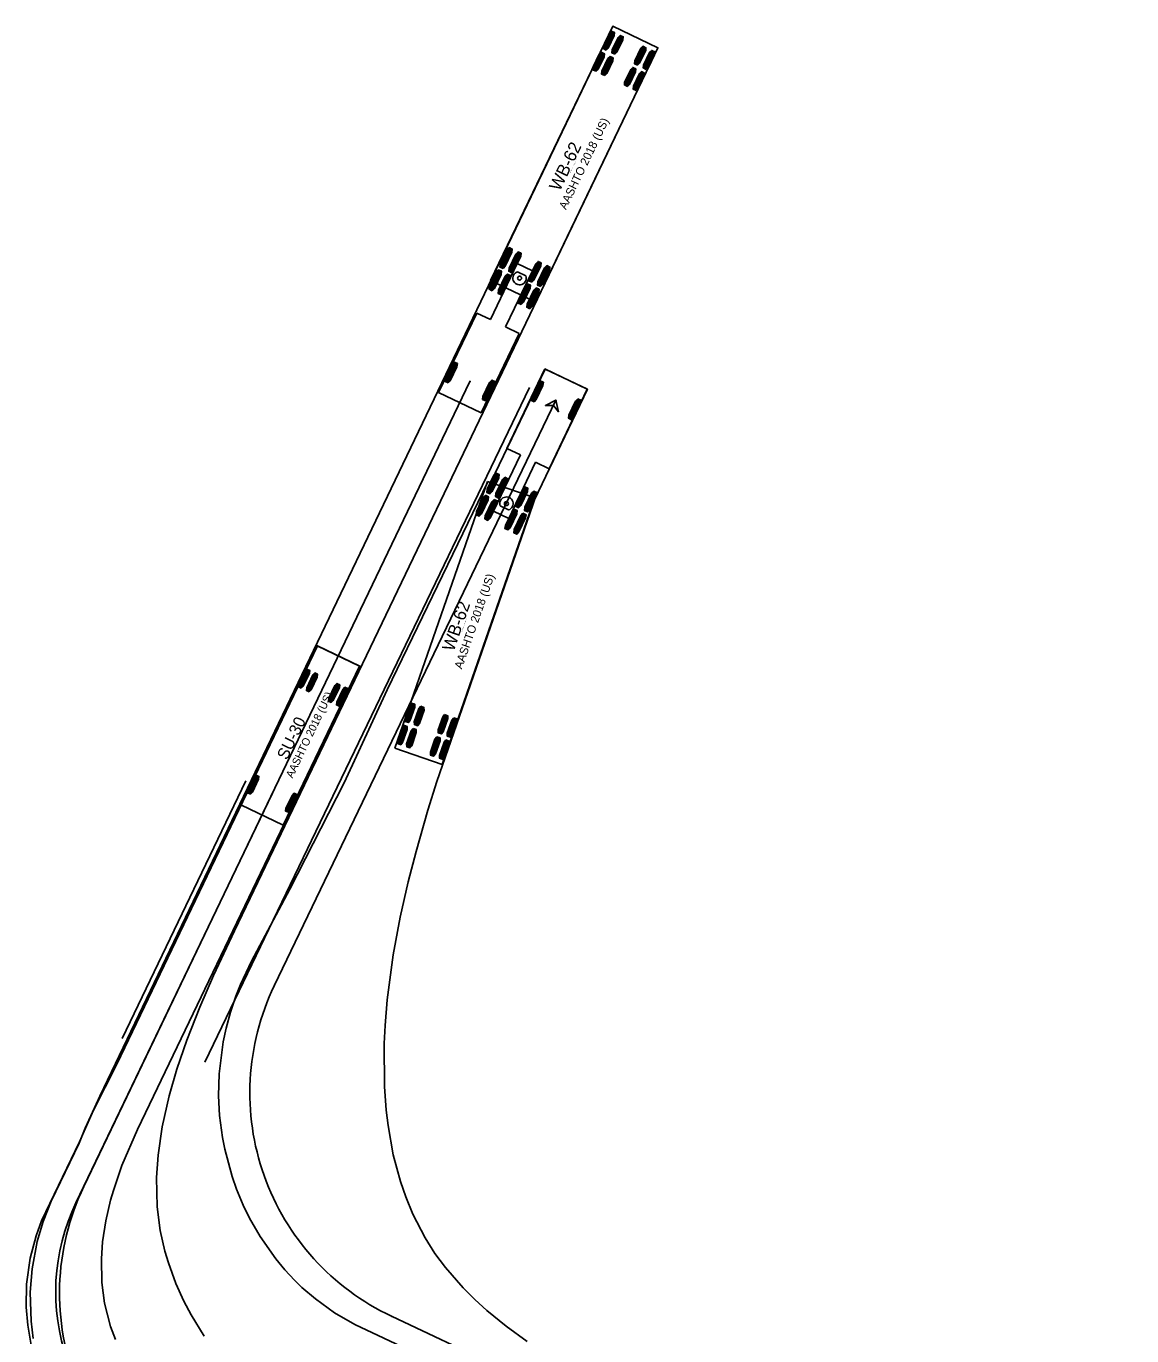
# Model space of a CAD drawing. Extents: x 186128 to 186702, y 352195 to 353183.
# Drawn here: x 186453 to 186641.2, y 352960 to 353182.7 of the extents above; entities that cross this region are included whole.
import ezdxf

# ---------------------------------------------------------------- set-up
doc = ezdxf.new("R2010")
doc.units = 0
doc.layers.add('SV_X_Control_Cells_Found', color=7, linetype='Continuous')
doc.layers.add('SV_X_Shot_Marker', color=7, linetype='Continuous')

msp = doc.modelspace()

# ---------------------------------------------------------------- linework, layer by layer
at = {"layer": 'SV_X_Control_Cells_Found'}
for p, q in [((186502.56, 353077.37), (186489.58, 353050.32)), ((186509.78, 353073.9), (186502.56, 353077.37)), ((186496.79, 353046.86), (186509.78, 353073.9)), ((186499.43, 353070.36), (186500.88, 353073.37)), ((186499.62, 353070.27), (186501.06, 353073.28)), ((186499.81, 353070.18), (186501.25, 353073.19)), ((186500.79, 353069.72), (186502.23, 353072.72)), ((186500.97, 353069.63), (186502.42, 353072.63)), ((186501.16, 353069.53), (186502.6, 353072.54)), ((186504.54, 353067.91), (186505.98, 353070.92)), ((186504.73, 353067.82), (186506.17, 353070.83)), ((186504.92, 353067.73), (186506.36, 353070.74)), ((186505.89, 353067.26), (186507.34, 353070.27)), ((186506.08, 353067.17), (186507.52, 353070.18)), ((186506.27, 353067.08), (186507.71, 353070.09)), ((186490.78, 353052.33), (186492.22, 353055.34)), ((186490.97, 353052.24), (186492.41, 353055.25)), ((186491.15, 353052.15), (186492.6, 353055.16)), ((186490.41, 353054.36), (186469.4, 353010.58)), ((186494.92, 353052.2), (186461.52, 352982.61)), ((186489.58, 353050.32), (186496.79, 353046.86)), ((186497.24, 353049.23), (186498.68, 353052.24)), ((186497.43, 353049.14), (186498.87, 353052.15)), ((186497.62, 353049.05), (186499.06, 353052.06)), ((186496.79, 353046.86), (186496.79, 353046.86))]:
    msp.add_line(p, q, dxfattribs=at)
for points in [[(186453.93, 352958.07), (186453.31, 352961.78), (186453.05, 352964.83), (186453.11, 352968.77), (186453.74, 352973.2), (186454.72, 352976.97), (186455.67, 352979.53), (186462.13, 352992.95), (186462.89, 352994.82), (186464.53, 352998.36), (186468.47, 353006.17), (186502.62, 353077.36), (186509.84, 353073.89), (186471.98, 352995.05), (186469.35, 352988.94), (186467.88, 352984.71), (186467.42, 352983.07), (186466.6, 352979.56), (186466.04, 352975.99), (186465.84, 352973.1), (186465.94, 352969.03), (186466.4, 352965.55), (186467.42, 352961.58), (186468.24, 352959.38)], [(186499.86, 353070.16), (186499.39, 353070.39), (186499.45, 353070.88), (186500.49, 353073.04), (186500.83, 353073.39), (186501.3, 353073.17), (186501.24, 353072.68), (186500.2, 353070.51), (186499.86, 353070.16)], [(186501.21, 353069.51), (186500.74, 353069.74), (186500.8, 353070.23), (186501.84, 353072.39), (186502.18, 353072.74), (186502.65, 353072.52), (186502.59, 353072.03), (186501.55, 353069.87), (186501.21, 353069.51)], [(186504.96, 353067.71), (186504.5, 353067.93), (186504.56, 353068.42), (186505.59, 353070.59), (186505.94, 353070.94), (186506.41, 353070.71), (186506.35, 353070.23), (186505.31, 353068.06), (186504.96, 353067.71)], [(186506.32, 353067.06), (186505.85, 353067.29), (186505.91, 353067.77), (186506.95, 353069.94), (186507.29, 353070.29), (186507.76, 353070.07), (186507.7, 353069.58), (186506.66, 353067.41), (186506.32, 353067.06)], [(186491.2, 353052.13), (186490.73, 353052.36), (186490.79, 353052.84), (186491.83, 353055.01), (186492.17, 353055.36), (186492.64, 353055.14), (186492.58, 353054.65), (186491.54, 353052.48), (186491.2, 353052.13)], [(186497.66, 353049.03), (186497.19, 353049.25), (186497.25, 353049.74), (186498.29, 353051.91), (186498.64, 353052.26), (186499.1, 353052.04), (186499.04, 353051.55), (186498.01, 353049.38), (186497.66, 353049.03)]]:
    msp.add_lwpolyline(points, dxfattribs=at)
for centre in [(186494.92, 353052.2), (186461.52, 352982.61), (186461.52, 352982.61)]:
    msp.add_circle(centre, 0.0417, dxfattribs=at)
msp.add_arc((186493.07, 352967.47), 35, 154.3603, 244.5505, dxfattribs=at)
at = {"layer": 'SV_X_Shot_Marker'}
for p, q in [((186552.86, 353182.75), (186532.09, 353139.47)), ((186551.28, 353178.91), (186552.7, 353181.88)), ((186551.48, 353178.81), (186552.91, 353181.78)), ((186551.69, 353178.71), (186553.12, 353181.68)), ((186560.53, 353179.07), (186552.86, 353182.75)), ((186552.76, 353178.19), (186554.19, 353181.17)), ((186552.97, 353178.09), (186554.4, 353181.07)), ((186553.18, 353177.99), (186554.6, 353180.97)), ((186556.62, 353176.34), (186558.05, 353179.31)), ((186539.76, 353135.79), (186560.53, 353179.07)), ((186549.54, 353175.3), (186550.97, 353178.27)), ((186549.75, 353175.2), (186551.18, 353178.18)), ((186549.96, 353175.1), (186551.39, 353178.08)), ((186551.03, 353174.59), (186552.46, 353177.56)), ((186551.24, 353174.49), (186552.67, 353177.46)), ((186551.45, 353174.39), (186552.87, 353177.36)), ((186556.83, 353176.24), (186558.26, 353179.21)), ((186557.04, 353176.14), (186558.47, 353179.11)), ((186558.11, 353175.62), (186559.54, 353178.6)), ((186558.32, 353175.52), (186559.75, 353178.5)), ((186558.53, 353175.43), (186559.95, 353178.4)), ((186554.89, 353172.73), (186556.32, 353175.71)), ((186555.1, 353172.63), (186556.53, 353175.61)), ((186555.31, 353172.53), (186556.74, 353175.51)), ((186556.38, 353172.02), (186557.81, 353174.99)), ((186556.59, 353171.92), (186558.02, 353174.89)), ((186556.79, 353171.82), (186558.22, 353174.79)), ((186533.72, 353141.76), (186535.31, 353145.06)), ((186533.93, 353141.66), (186535.52, 353144.97)), ((186534.14, 353141.56), (186535.72, 353144.87)), ((186535.21, 353141.05), (186536.8, 353144.35)), ((186535.42, 353140.95), (186537, 353144.25)), ((186535.62, 353140.85), (186537.21, 353144.15)), ((186536.62, 353142.4), (186532.04, 353132.84)), ((186539.21, 353141.16), (186536.62, 353142.4)), ((186538.62, 353139.41), (186540.21, 353142.71)), ((186538.83, 353139.31), (186540.42, 353142.61)), ((186539.04, 353139.21), (186540.62, 353142.52)), ((186540.11, 353138.69), (186541.7, 353142)), ((186540.32, 353138.6), (186541.9, 353141.9)), ((186540.52, 353138.5), (186542.11, 353141.8)), ((186531.91, 353137.97), (186533.49, 353141.28)), ((186532.09, 353139.47), (186539.76, 353135.79)), ((186532.11, 353137.87), (186533.7, 353141.18)), ((186532.32, 353137.77), (186533.91, 353141.08)), ((186533.39, 353137.26), (186534.98, 353140.56)), ((186533.6, 353137.16), (186535.19, 353140.47)), ((186533.81, 353137.06), (186535.39, 353140.37)), ((186534.62, 353131.6), (186539.21, 353141.16)), ((186538.09, 353140.27), (186536.63, 353140.97)), ((186536.8, 353135.62), (186538.39, 353138.93)), ((186537.01, 353135.52), (186538.6, 353138.83)), ((186537.22, 353135.42), (186538.8, 353138.73)), ((186538.29, 353134.91), (186539.88, 353138.21)), ((186538.5, 353134.81), (186540.09, 353138.11)), ((186538.71, 353134.71), (186540.29, 353138.02)), ((186539.76, 353135.79), (186539.76, 353135.79)), ((186529.72, 353133.96), (186523.23, 353120.43)), ((186532.04, 353132.84), (186529.72, 353133.96)), ((186530.45, 353116.97), (186536.94, 353130.49)), ((186536.94, 353130.49), (186534.62, 353131.6)), ((186524.38, 353122.29), (186525.96, 353125.59)), ((186524.58, 353122.19), (186526.17, 353125.49)), ((186524.79, 353122.09), (186526.38, 353125.39)), ((186541.32, 353124.46), (186534.84, 353110.93)), ((186548.53, 353121), (186541.32, 353124.46)), ((186541.32, 353124.46), (186541.32, 353124.46)), ((186462.85, 352985.38), (186528.57, 353122.31)), ((186530.76, 353119.22), (186532.35, 353122.53)), ((186530.97, 353119.12), (186532.56, 353122.43)), ((186531.18, 353119.02), (186532.76, 353122.33)), ((186540.59, 353122.4), (186539, 353119.1)), ((186540.8, 353122.3), (186539.21, 353119)), ((186541.01, 353122.2), (186539.42, 353118.9)), ((186483.46, 353006.54), (186538.69, 353121.29)), ((186495.26, 353019.53), (186543.2, 353119.12)), ((186523.23, 353120.43), (186530.45, 353116.97)), ((186542.05, 353107.47), (186548.53, 353121)), ((186546.98, 353119.34), (186545.39, 353116.04)), ((186547.19, 353119.24), (186545.6, 353115.94)), ((186547.39, 353119.14), (186545.8, 353115.84)), ((186530.45, 353116.97), (186530.45, 353116.97)), ((186534.84, 353110.93), (186537.15, 353109.82)), ((186537.15, 353109.82), (186532.57, 353100.26)), ((186535.16, 353099.02), (186539.74, 353108.58)), ((186539.74, 353108.58), (186542.05, 353107.47)), ((186533.07, 353106.71), (186531.49, 353103.4)), ((186533.28, 353106.61), (186531.69, 353103.31)), ((186533.48, 353106.51), (186531.9, 353103.21)), ((186534.56, 353106), (186532.97, 353102.69)), ((186534.76, 353105.9), (186533.18, 353102.59)), ((186534.97, 353105.8), (186533.39, 353102.49)), ((186531.58, 353105.29), (186515.79, 353059.96)), ((186539.61, 353102.5), (186531.58, 353105.29)), ((186531.58, 353105.29), (186531.58, 353105.29)), ((186537.97, 353104.36), (186536.39, 353101.06)), ((186538.18, 353104.26), (186536.59, 353100.96)), ((186538.38, 353104.17), (186536.8, 353100.86)), ((186539.46, 353103.65), (186537.87, 353100.34)), ((186539.66, 353103.55), (186538.08, 353100.24)), ((186523.82, 353057.17), (186539.61, 353102.5)), ((186531.25, 353102.92), (186529.67, 353099.62)), ((186531.46, 353102.82), (186529.88, 353099.52)), ((186531.67, 353102.73), (186530.08, 353099.42)), ((186532.74, 353102.21), (186531.16, 353098.9)), ((186532.95, 353102.11), (186531.36, 353098.81)), ((186533.16, 353102.01), (186531.57, 353098.71)), ((186539.87, 353103.45), (186538.29, 353100.15)), ((186532.57, 353100.26), (186535.16, 353099.02)), ((186533.69, 353101.16), (186535.15, 353100.46)), ((186536.15, 353100.58), (186534.57, 353097.27)), ((186536.36, 353100.48), (186534.78, 353097.17)), ((186536.57, 353100.38), (186534.98, 353097.07)), ((186537.64, 353099.86), (186536.06, 353096.56)), ((186537.85, 353099.76), (186536.26, 353096.46)), ((186538.06, 353099.66), (186536.47, 353096.36)), ((186518.69, 353067.58), (186517.61, 353064.47)), ((186518.91, 353067.51), (186517.82, 353064.39)), ((186519.12, 353067.43), (186518.04, 353064.32)), ((186520.25, 353067.04), (186519.16, 353063.93)), ((186520.47, 353066.97), (186519.38, 353063.85)), ((186520.68, 353066.89), (186519.6, 353063.77)), ((186524.29, 353065.63), (186523.21, 353062.52)), ((186517.38, 353063.81), (186516.29, 353060.69)), ((186517.59, 353063.73), (186516.51, 353060.61)), ((186517.81, 353063.66), (186516.72, 353060.54)), ((186524.51, 353065.56), (186523.43, 353062.44)), ((186524.73, 353065.48), (186523.64, 353062.37)), ((186525.85, 353065.09), (186524.77, 353061.97)), ((186526.07, 353065.01), (186524.98, 353061.9)), ((186526.29, 353064.94), (186525.2, 353061.82)), ((186518.93, 353063.26), (186517.85, 353060.15)), ((186519.15, 353063.19), (186518.07, 353060.07)), ((186519.37, 353063.11), (186518.28, 353060)), ((186522.98, 353061.86), (186521.89, 353058.74)), ((186523.2, 353061.78), (186522.11, 353058.66)), ((186523.41, 353061.7), (186522.33, 353058.59)), ((186524.54, 353061.31), (186523.45, 353058.2)), ((186524.75, 353061.24), (186523.67, 353058.12)), ((186524.97, 353061.16), (186523.88, 353058.05)), ((186515.79, 353059.96), (186523.82, 353057.17)), ((186469.4, 353010.58), (186490.41, 353054.36)), ((186515.24, 352963.3), (186641.2, 352904.08))]:
    msp.add_line(p, q, dxfattribs=at)
for points in [[(186454.24, 352959.52), (186453.88, 352962.47), (186453.74, 352967.42), (186454.07, 352971.39), (186454.93, 352976.02), (186455.91, 352979.43), (186457.29, 352982.91), (186462.04, 352992.75), (186463.06, 352995.31), (186465.56, 353000.72), (186552.86, 353182.74), (186560.54, 353179.07), (186488.49, 353028.87), (186484.95, 353021.26), (186482.62, 353015.91), (186480.38, 353010.27), (186478.68, 353005.35), (186477.37, 353000.79), (186476.19, 352995.54), (186475.5, 352990.72), (186475.23, 352986.91), (186475.33, 352981.92), (186475.86, 352977.92), (186476.64, 352974.38), (186477.24, 352972.41), (186478.51, 352968.9), (186479.89, 352965.88), (186481.11, 352963.55), (186483.34, 352959.94)], [(186551.74, 353178.68), (186551.22, 353178.93), (186551.27, 353179.42), (186552.3, 353181.56), (186552.65, 353181.91), (186553.17, 353181.66), (186553.12, 353181.17), (186552.1, 353179.02), (186551.74, 353178.68)], [(186553.23, 353177.97), (186552.71, 353178.22), (186552.76, 353178.71), (186553.78, 353180.85), (186554.14, 353181.19), (186554.66, 353180.94), (186554.61, 353180.45), (186553.58, 353178.31), (186553.23, 353177.97)], [(186557.09, 353176.12), (186556.57, 353176.36), (186556.62, 353176.85), (186557.65, 353179), (186558, 353179.34), (186558.52, 353179.09), (186558.47, 353178.6), (186557.44, 353176.46), (186557.09, 353176.12)], [(186550.01, 353175.08), (186549.49, 353175.32), (186549.54, 353175.81), (186550.57, 353177.96), (186550.92, 353178.3), (186551.44, 353178.05), (186551.39, 353177.56), (186550.36, 353175.42), (186550.01, 353175.08)], [(186551.5, 353174.36), (186550.98, 353174.61), (186551.03, 353175.1), (186552.05, 353177.24), (186552.41, 353177.59), (186552.92, 353177.34), (186552.88, 353176.85), (186551.85, 353174.7), (186551.5, 353174.36)], [(186558.58, 353175.4), (186558.06, 353175.65), (186558.11, 353176.14), (186559.13, 353178.28), (186559.49, 353178.62), (186560, 353178.38), (186559.96, 353177.89), (186558.93, 353175.74), (186558.58, 353175.4)], [(186555.36, 353172.51), (186554.84, 353172.76), (186554.89, 353173.25), (186555.92, 353175.39), (186556.27, 353175.73), (186556.79, 353175.48), (186556.74, 353174.99), (186555.71, 353172.85), (186555.36, 353172.51)], [(186556.85, 353171.8), (186556.33, 353172.04), (186556.37, 353172.53), (186557.4, 353174.68), (186557.76, 353175.02), (186558.27, 353174.77), (186558.23, 353174.28), (186557.2, 353172.14), (186556.85, 353171.8)], [(186534.19, 353141.54), (186533.67, 353141.78), (186533.74, 353142.32), (186534.88, 353144.7), (186535.26, 353145.09), (186535.77, 353144.84), (186535.71, 353144.3), (186534.57, 353141.92), (186534.19, 353141.54)], [(186535.68, 353140.82), (186535.16, 353141.07), (186535.23, 353141.61), (186536.37, 353143.99), (186536.75, 353144.38), (186537.26, 353144.13), (186537.2, 353143.59), (186536.05, 353141.21), (186535.68, 353140.82)], [(186539.09, 353139.19), (186538.57, 353139.43), (186538.64, 353139.97), (186539.78, 353142.35), (186540.16, 353142.74), (186540.67, 353142.49), (186540.61, 353141.95), (186539.46, 353139.57), (186539.09, 353139.19)], [(186540.57, 353138.47), (186540.06, 353138.72), (186540.13, 353139.26), (186541.27, 353141.64), (186541.65, 353142.02), (186542.16, 353141.78), (186542.09, 353141.24), (186540.95, 353138.86), (186540.57, 353138.47)], [(186532.37, 353137.75), (186531.86, 353138), (186531.92, 353138.53), (186533.06, 353140.91), (186533.44, 353141.3), (186533.96, 353141.06), (186533.89, 353140.52), (186532.75, 353138.14), (186532.37, 353137.75)], [(186533.86, 353137.04), (186533.34, 353137.28), (186533.41, 353137.82), (186534.55, 353140.2), (186534.93, 353140.59), (186535.45, 353140.34), (186535.38, 353139.8), (186534.24, 353137.42), (186533.86, 353137.04)], [(186537.27, 353135.4), (186536.75, 353135.65), (186536.82, 353136.18), (186537.96, 353138.56), (186538.34, 353138.95), (186538.86, 353138.7), (186538.79, 353138.17), (186537.65, 353135.79), (186537.27, 353135.4)], [(186538.76, 353134.68), (186538.24, 353134.93), (186538.31, 353135.47), (186539.45, 353137.85), (186539.83, 353138.24), (186540.34, 353137.99), (186540.28, 353137.45), (186539.13, 353135.07), (186538.76, 353134.68)], [(186518.86, 352957.26), (186508.96, 352961.88), (186505.51, 352963.88), (186502.26, 352966.25), (186499.97, 352968.21), (186498.72, 352969.43), (186497.05, 352971.23), (186495.51, 352973.1), (186492.85, 352976.88), (186491.04, 352979.99), (186489.96, 352982.22), (186488.85, 352984.91), (186488.09, 352987.08), (186486.84, 352991.74), (186486.45, 352993.74), (186485.96, 352997.48), (186485.79, 353000.83), (186485.89, 353004.53), (186486.58, 353009.98), (186487.07, 353012.31), (186487.83, 353015.06), (186488.71, 353017.76), (186489.5, 353019.76), (186491.4, 353023.73), (186497.9, 353035.93), (186507.15, 353054.04), (186514.5, 353069.85), (186528.18, 353098.2), (186531.63, 353105.26), (186532.12, 353105.19), (186541.37, 353124.42), (186548.56, 353121), (186539.57, 353102.2), (186539.24, 353101.35), (186522.93, 353054.27), (186521.39, 353049.38), (186519.39, 353042.39), (186518.04, 353037.18), (186516.7, 353031.17), (186515.52, 353024.81), (186514.47, 353017.13), (186514.11, 353012.77), (186513.98, 353009.68), (186514.01, 353002.4), (186514.3, 352998.37), (186514.63, 352995.74), (186515.52, 352990.79), (186516.73, 352986.23), (186517.65, 352983.6), (186518.86, 352980.68), (186520.93, 352976.65), (186522.6, 352973.99), (186524.38, 352971.63), (186527.43, 352968.12), (186529.4, 352966.15), (186531.46, 352964.28), (186534.71, 352961.62), (186538.29, 352959.03)], [(186524.84, 353122.06), (186524.33, 353122.31), (186524.39, 353122.85), (186525.54, 353125.23), (186525.91, 353125.62), (186526.43, 353125.37), (186526.36, 353124.83), (186525.22, 353122.45), (186524.84, 353122.06)], [(186531.23, 353119), (186530.71, 353119.25), (186530.78, 353119.78), (186531.92, 353122.16), (186532.3, 353122.55), (186532.81, 353122.3), (186532.75, 353121.77), (186531.61, 353119.39), (186531.23, 353119)], [(186540.54, 353122.43), (186541.06, 353122.18), (186540.99, 353121.64), (186539.84, 353119.26), (186539.47, 353118.87), (186538.95, 353119.12), (186539.02, 353119.66), (186540.16, 353122.04), (186540.54, 353122.43)], [(186543.2, 353119.12), (186541.41, 353118.22), (186542.76, 353118.22), (186543.61, 353117.16), (186543.2, 353119.12)], [(186546.93, 353119.36), (186547.44, 353119.12), (186547.38, 353118.58), (186546.23, 353116.2), (186545.85, 353115.81), (186545.34, 353116.06), (186545.41, 353116.6), (186546.55, 353118.98), (186546.93, 353119.36)], [(186533.02, 353106.74), (186533.53, 353106.49), (186533.47, 353105.95), (186532.33, 353103.57), (186531.95, 353103.18), (186531.43, 353103.43), (186531.5, 353103.97), (186532.64, 353106.35), (186533.02, 353106.74)], [(186534.51, 353106.02), (186535.02, 353105.78), (186534.96, 353105.24), (186533.82, 353102.86), (186533.44, 353102.47), (186532.92, 353102.72), (186532.99, 353103.25), (186534.13, 353105.63), (186534.51, 353106.02)], [(186537.92, 353104.39), (186538.43, 353104.14), (186538.37, 353103.6), (186537.23, 353101.22), (186536.85, 353100.83), (186536.33, 353101.08), (186536.4, 353101.62), (186537.54, 353104), (186537.92, 353104.39)], [(186539.41, 353103.67), (186539.92, 353103.43), (186539.86, 353102.89), (186538.71, 353100.51), (186538.34, 353100.12), (186537.82, 353100.37), (186537.89, 353100.91), (186539.03, 353103.29), (186539.41, 353103.67)], [(186531.2, 353102.95), (186531.72, 353102.7), (186531.65, 353102.16), (186530.51, 353099.78), (186530.13, 353099.39), (186529.62, 353099.64), (186529.69, 353100.18), (186530.83, 353102.56), (186531.2, 353102.95)], [(186532.69, 353102.24), (186533.21, 353101.99), (186533.14, 353101.45), (186532, 353099.07), (186531.62, 353098.68), (186531.11, 353098.93), (186531.17, 353099.47), (186532.31, 353101.85), (186532.69, 353102.24)], [(186536.1, 353100.6), (186536.62, 353100.35), (186536.55, 353099.82), (186535.41, 353097.43), (186535.03, 353097.05), (186534.52, 353097.29), (186534.59, 353097.83), (186535.73, 353100.21), (186536.1, 353100.6)], [(186537.59, 353099.89), (186538.11, 353099.64), (186538.04, 353099.1), (186536.9, 353096.72), (186536.52, 353096.33), (186536.01, 353096.58), (186536.07, 353097.12), (186537.21, 353099.5), (186537.59, 353099.89)], [(186518.64, 353067.6), (186519.18, 353067.41), (186519.19, 353066.92), (186518.41, 353064.68), (186518.09, 353064.3), (186517.55, 353064.49), (186517.54, 353064.98), (186518.32, 353067.22), (186518.64, 353067.6)], [(186520.2, 353067.06), (186520.74, 353066.87), (186520.75, 353066.38), (186519.97, 353064.14), (186519.65, 353063.76), (186519.11, 353063.94), (186519.1, 353064.44), (186519.88, 353066.68), (186520.2, 353067.06)], [(186524.24, 353065.65), (186524.78, 353065.46), (186524.79, 353064.97), (186524.01, 353062.73), (186523.7, 353062.35), (186523.16, 353062.54), (186523.14, 353063.03), (186523.93, 353065.27), (186524.24, 353065.65)], [(186517.32, 353063.83), (186517.86, 353063.64), (186517.87, 353063.14), (186517.09, 353060.9), (186516.78, 353060.52), (186516.24, 353060.71), (186516.23, 353061.2), (186517.01, 353063.45), (186517.32, 353063.83)], [(186525.8, 353065.11), (186526.34, 353064.92), (186526.35, 353064.43), (186525.57, 353062.18), (186525.25, 353061.8), (186524.71, 353061.99), (186524.7, 353062.49), (186525.48, 353064.73), (186525.8, 353065.11)], [(186518.88, 353063.28), (186519.42, 353063.09), (186519.43, 353062.6), (186518.65, 353060.36), (186518.34, 353059.98), (186517.8, 353060.17), (186517.78, 353060.66), (186518.57, 353062.9), (186518.88, 353063.28)], [(186522.93, 353061.87), (186523.47, 353061.69), (186523.48, 353061.19), (186522.7, 353058.95), (186522.38, 353058.57), (186521.84, 353058.76), (186521.83, 353059.25), (186522.61, 353061.49), (186522.93, 353061.87)], [(186524.48, 353061.33), (186525.02, 353061.14), (186525.03, 353060.65), (186524.25, 353058.41), (186523.94, 353058.03), (186523.4, 353058.22), (186523.39, 353058.71), (186524.17, 353060.95), (186524.48, 353061.33)]]:
    msp.add_lwpolyline(points, dxfattribs=at)
msp.add_lwpolyline([(186543.2, 353119.12), (186541.41, 353118.22), (186542.76, 353118.22), (186543.61, 353117.16)], close=True, dxfattribs=at)
for centre, radius in [((186537.01, 353139.89), 0.34), ((186528.57, 353122.31), 0.0417), ((186543.2, 353119.12), 0.0417), ((186534.77, 353101.53), 0.34), ((186495.26, 353019.53), 0.0417), ((186495.26, 353019.53), 0.0417), ((186462.85, 352985.38), 0.0417), ((186462.85, 352985.38), 0.0417), ((186515.24, 352963.3), 0.0417), ((186515.24, 352963.3), 0.0417)]:
    msp.add_circle(centre, radius, dxfattribs=at)
for centre, radius, start, end in [((186537.01, 353139.89), 1.14, 109.3603, 19.3603), ((186534.77, 353101.53), 1.14, 289.3955, 199.3955), ((186533.11, 353001.31), 42, 154.2974, 244.8189), ((186500.72, 352967.21), 42, 154.3603, 249.5711)]:
    msp.add_arc(centre, radius, start, end, dxfattribs=at)

# ---------------------------------------------------------------- texts
at = {"layer": 'SV_X_Control_Cells_Found'}
for s, height, p in [('AASHTO 2018 (US)', 1.3333, (186498.37, 353054.74)), ('SU-30', 2, (186497.43, 353057.8)), ('(c) 2025 Transoft Solutions, Inc. All rights reserved.', 0.08, (186499.01, 353060.62))]:
    msp.add_text(s, height=height, rotation=64.3603, dxfattribs=at).set_placement(p)
at = {"layer": 'SV_X_Shot_Marker'}
for s, height, rotation, p in [('AASHTO 2018 (US)', 1.4167, 64.3603, (186544.92, 353151.44)), ('WB-62', 2.125, 64.3603, (186543.86, 353154.55)), ('(c) 2025 Transoft Solutions, Inc. All rights reserved.', 0.085, 64.3603, (186545.6, 353157.68)), ('AASHTO 2018 (US)', 1.4167, 70.8013, (186527.19, 353073.29)), ('WB-62', 2.125, 70.8013, (186525.79, 353076.27)), ('(c) 2025 Transoft Solutions, Inc. All rights reserved.', 0.085, 70.8013, (186527.17, 353079.57))]:
    msp.add_text(s, height=height, rotation=rotation, dxfattribs=at).set_placement(p)

doc.saveas('drawing.dxf')
